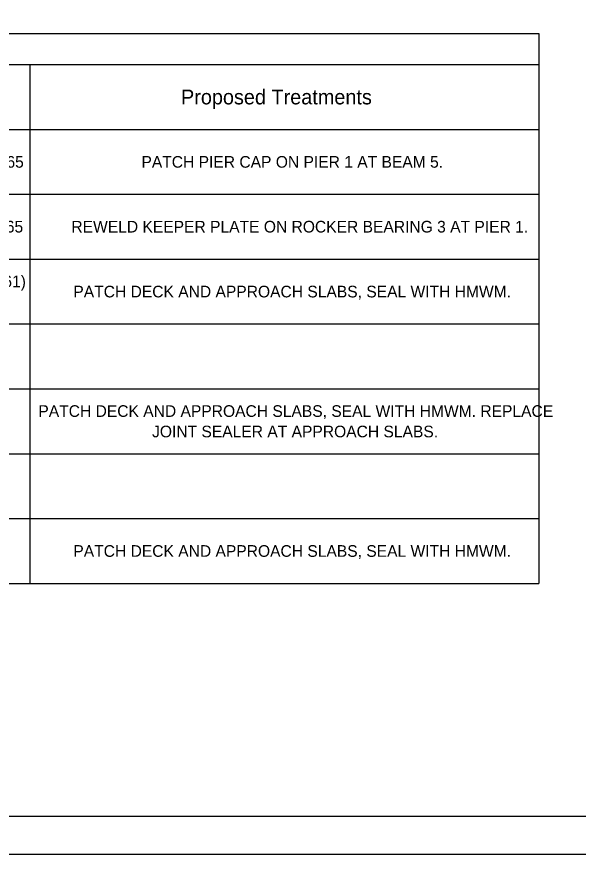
# Model space of a CAD drawing. Extents: x -29.6 to 34, y 0 to 22.
# Drawn here: x 14.72 to 22.13, y 0 to 11.06 of the extents above; entities that cross this region are included whole.
import ezdxf

# ---------------------------------------------------------------- set-up
doc = ezdxf.new("R2010")
doc.units = 0
for name, color, linetype in [('SH_Border', 7, 'Continuous'), ('SH_Cut_Line', 7, 'Continuous'), ('SH_Text', 7, 'Continuous')]:
    doc.layers.add(name, color=color, linetype=linetype)

msp = doc.modelspace()

# ---------------------------------------------------------------- linework, layer by layer
at = {"layer": 'SH_Border'}
msp.add_lwpolyline([(1.5, 21.5), (33.5, 21.5), (33.5, 0.5), (1.5, 0.5)], close=True, dxfattribs=at)
at = {"layer": 'SH_Cut_Line'}
msp.add_lwpolyline([(0, 0), (34, 0), (34, 22), (0, 22)], close=True, dxfattribs=at)
at = {"layer": 'SH_Text'}
for p, q in [((2.62, 10.841), (21.611, 10.841)), ((21.611, 10.841), (21.611, 3.577)), ((2.62, 10.429), (21.611, 10.429)), ((14.891, 10.429), (14.891, 3.577)), ((2.62, 9.572), (21.611, 9.572)), ((2.62, 8.716), (21.611, 8.716)), ((2.62, 7.859), (21.611, 7.859)), ((2.62, 7.003), (21.611, 7.003)), ((2.62, 6.146), (21.611, 6.146)), ((2.62, 5.29), (21.611, 5.29)), ((2.62, 4.433), (21.611, 4.433)), ((2.62, 3.577), (21.611, 3.577))]:
    msp.add_line(p, q, dxfattribs=at)

# ---------------------------------------------------------------- texts
for s, height, p in [('Proposed Treatments', 0.196, (16.887, 9.903)), ('IR 70 WB OVER SR 265', 0.154, (12.545, 9.067)), ('PATCH PIER CAP ON PIER 1 AT BEAM 5.', 0.154, (16.365, 9.067)), ('IR 70 EB OVER SR 265', 0.154, (12.594, 8.211)), ('REWELD KEEPER PLATE ON ROCKER BEARING 3 AT PIER 1.', 0.154, (15.44, 8.211)), ('CARLISLE RD (CR 761) ', 0.154, (12.596, 7.489)), ('PATCH DECK AND APPROACH SLABS, SEAL WITH HMWM.', 0.154, (15.466, 7.354)), ('PATCH DECK AND APPROACH SLABS, SEAL WITH HMWM. REPLACE ', 0.154, (15.004, 5.776)), ('JOINT SEALER AT APPROACH SLABS.', 0.154, (16.505, 5.506)), ('PATCH DECK AND APPROACH SLABS, SEAL WITH HMWM.', 0.154, (15.466, 3.928))]:
    msp.add_text(s, height=height, dxfattribs=at).set_placement(p)

doc.saveas('drawing.dxf')
